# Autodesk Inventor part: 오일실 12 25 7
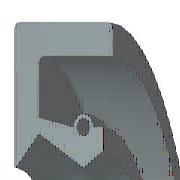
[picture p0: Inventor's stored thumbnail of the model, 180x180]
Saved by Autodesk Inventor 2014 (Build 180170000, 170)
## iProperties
IsCustomPart: 1
Created: 2012-02
Part Number: 오일실 12 25 7
Material: 고무
Description: 오일-실
Document SubType Name: Modeling
Standard: KS B 2804
Designer: test
Standards Organization: KS
Language: ko-KR
Size Designation: D - 12 25 7
Categories: <MemberInstance><Categories><Category DisplayName="샤프트 부품" InternalName="7f7aeb1f-a693-4053-b835-cee3144e0d98" Mnemonic="SHFT"><Category DisplayName="실링" Intern
Density: 0.93 g/cm^3
Appearance: 고무 - 검은색 - 버전 1.1
Mass: 1.51442 g
Surface Area: 21.8326 cm^2
Volume: 1.6284 cm^3
Author: test
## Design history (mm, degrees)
revolve "본체" stored, may be unused: angle "d17" = 90 deg
revolve "스프링1" stored, may be unused: angle "d18" = 90 deg
body "Solid1"
sketch "스케치1"
  geometry: L1 (0, 12.5)-(7, 12.5); L2 (7, 10.75)-(1.75, 10.75); L3 (1.75, 7.75)-(4.9, 6); L4 (4.9, 6)-(0, 6); L5 (0, 0)-(9.586, 0) reference; L6 (4.9, 6)-(6.3, 6.875); L7 (0, 18)-(0, -3) reference; L8 (-1.941, 0)-(11.507, 0) reference; L9 (4.2, 8.1)-(1.75, 8.59); L10 (1.75, 8.59)-(1.75, 10.75); L11 (0, 12.5)-(0, 6.088); L12 (4.9, 6)-(0, 6); L13 (1.75, 7.75)-(0.152, 6.028); L14 (7, 12.5)-(7, 10.75); L15 (5.6, 8.1)-(6.3, 8.1); L16 (6.3, 8.1)-(6.3, 6.875); C1 r 0.455 at (4.9, 8.1); A1 r 0.7 centre (4.9, 8.1) between (5.6, 8.1) and (4.2, 8.1); A2 r 0.088 centre (0.088, 6.088) between (0, 6.088) and (0.152, 6.028); 1 further point
  constraints: 28 end point, 5 horizontal alignment, 5 point on line, 4 point on circle, 4 vertical alignment, 3 centre point, 3 tangent, 2 collinear, 2 horizontal, 2 perpendicular, 1 coincident, 1 parallel
  dimensions: "d0" = 25 diameter of L1 L5 (= SD2); "d1" = 1.75 distance of L1.end L2.start (= SD); "d2" = 0.91 diameter of C1 (= SPDI); "d3" = 1.4 diameter of A1 (= SPDA); "d4" = 12 diameter of L3.end L5 (= NND); "d5" = 15.5 diameter of L3.start L5 (= TKDM); "d7" = 17.18 diameter of L9.end L5 (= TKDM + 0.24 x SWDT); "d8" = 1.75 distance between parallel lines of L11 L10 (= SD); "d9" = 4.9 distance from line of L11 C1.centre (= SPDST); "d10" = 16.2 diameter of C1.centre L5 (= HLDM); "d11" = 0.0875 radius of A2 (= 0.25 x LAB); "d12" = 6.3 distance between parallel lines of L11 L16 (= SDI); "d13" = 13.75 diameter of L6.end L5 (= ABDM); "d14" = 7 distance from line of L11 L1.end (= SWDT)
fillet "모깎기1" dims "d6" = 0.3 (= RR)
other parameters: "SD2" = 25 [user parameter; used in 1 equation term], "SWDT" = 7 [user parameter; used in 2 equation terms], "RR" = 0.3 [user parameter; used in 1 equation term], "SD" = 1.75 [user parameter; used in 2 equation terms], "NND" = 12 [user parameter; used in 1 equation term], "SPDA" = 1.4 [user parameter; used in 1 equation term], "SPDI" = 0.91 [user parameter; used in 1 equation term], "TKDM" = 15.5 [user parameter; used in 2 equation terms], "HLDM" = 16.2 [user parameter; used in 1 equation term], "ABDM" = 13.75 [user parameter; used in 1 equation term], "SDI" = 6.3 [user parameter; used in 1 equation term], "SPDST" = 4.9 [user parameter; used in 1 equation term], "LAB" = 0.35 [user parameter; used in 1 equation term], "d15" = 0, "d16" = 0, "d19" = 0
